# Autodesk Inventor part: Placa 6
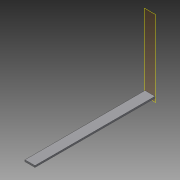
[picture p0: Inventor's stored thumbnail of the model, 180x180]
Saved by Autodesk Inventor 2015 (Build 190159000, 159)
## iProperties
Created: 2015-04
Part Number: Placa 6
Material: Generic
Document SubType Name: Modeling
Designer: suporte
Density: 1 g/cm^3
Appearance: Default
Author: suporte
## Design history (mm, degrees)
workplane "Work Plane1"
sketch "Sketch1"
  geometry: L1 (9.783, -259.3)-(-9.783, -259.3) reference; L2 (-37.5, -259.3)-(37.5, -259.3) reference; L3 (-50, -346.8)-(-50, -259.3) reference; L4 (50, -359.3)-(50, 359.3) reference; L5 (50, -259.3)-(-50, -259.3); L6 (-50, -259.3)-(-50, -246.8); L7 (-50, -246.8)-(50, -246.8)
  constraints: 8 end point, 2 perpendicular, 2 point on line, 1 horizontal, 1 vertical, 2 other
  dimensions: "d3" = 12.5 distance of L3.end L6.end
extrude "Extrusion1" new body sketch "Sketch1" distance "d1" = 900; taper "d2" = 0 deg
body "Solid1"
node "Reference1"
node "Reference2"
node "Reference3"
